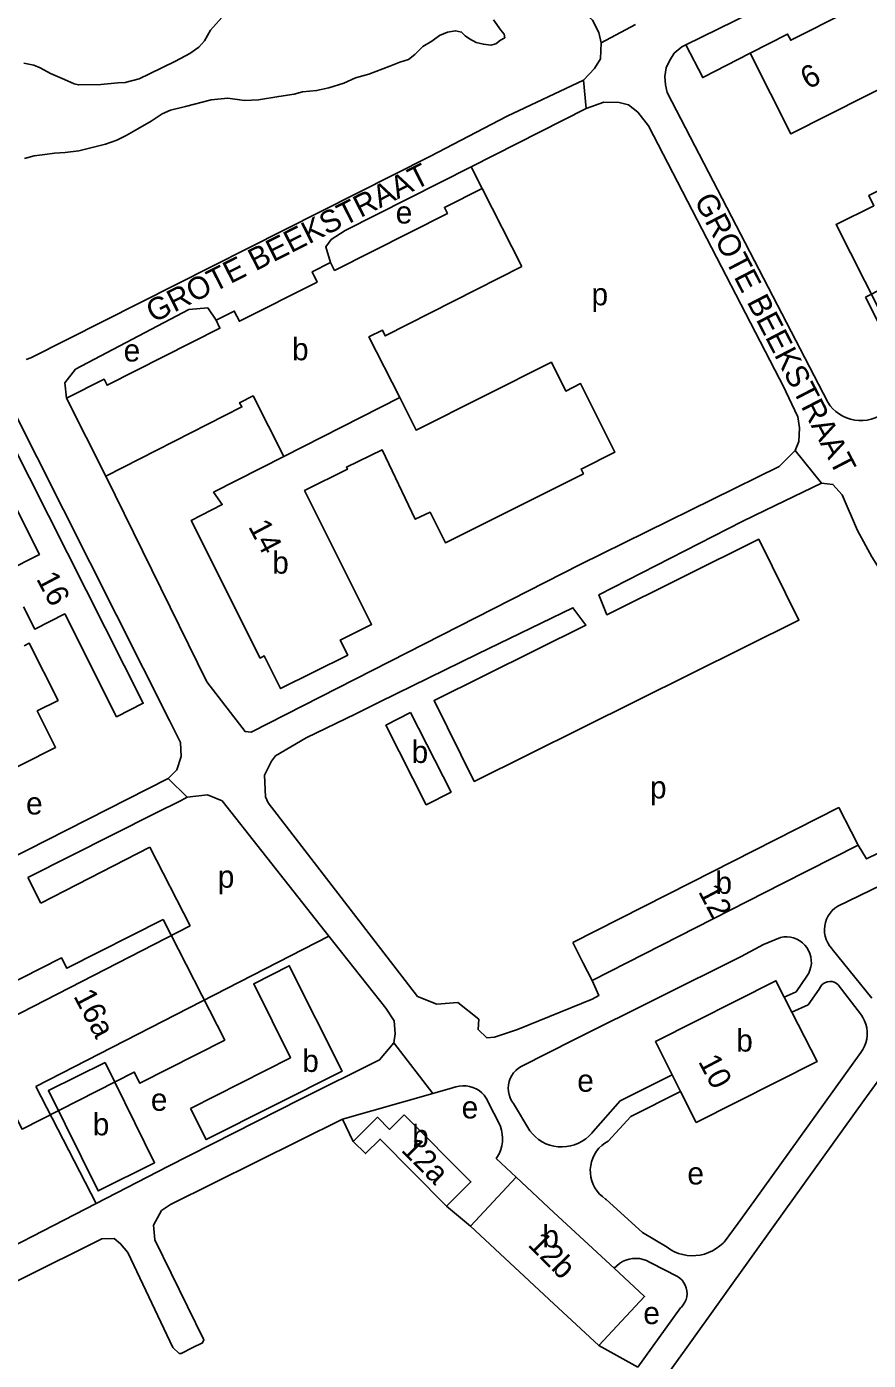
# Model space of a CAD drawing. Extents: x 158142 to 159655, y 385262 to 387204.
# Drawn here: x 158905.5 to 159056.3, y 386164.4 to 386403.5 of the extents above; entities that cross this region are included whole.
import ezdxf

# ---------------------------------------------------------------- set-up
doc = ezdxf.new("R2010")
doc.units = 0
for name, color, linetype in [('BLT_Basislijn', 7, 'Continuous'), ('BLT_Bebouwing', 7, 'Continuous'), ('BLT_Centroide', 7, 'Continuous'), ('BLT_Huisnummer', 7, 'Continuous'), ('BLT_Huisnummer_zonder_bebouwing', 7, 'Continuous'), ('BLT_Onderverdeling_panden', 7, 'Continuous'), ('BLT_Plantopo', 7, 'Continuous'), ('BLT_Straatnaam_verkleind', 7, 'Continuous'), ('BLT_Vlakafsluiter', 7, 'Continuous')]:
    doc.layers.add(name, color=color, linetype=linetype)

msp = doc.modelspace()

# ---------------------------------------------------------------- linework, layer by layer
at = {"layer": 'BLT_Basislijn'}
for p, q in [((159020.29, 386391.67), (159049.1, 386336.14)), ((158985.14, 386378.37), (159005.77, 386388.83)), ((158987.12, 386374.45), (158985.14, 386378.37)), ((158927.54, 386256.37), (158908.01, 386246.35)), ((158927.54, 386256.37), (158934.79, 386242.24)), ((158905.66, 386250.93), (158908.01, 386246.35)), ((158934.79, 386242.24), (158891.45, 386220.02)), ((158959.66, 386240.41), (158907.15, 386213.49)), ((159037.56, 386238.92), (159033.57, 386236.8)), ((159040.58, 386240.2), (159037.56, 386238.92)), ((159049.87, 386238.11), (159056.95, 386229.28)), ((159045.34, 386233.23), (159043.4, 386230.42)), ((159050.92, 386231.72), (159055.1, 386226.26)), ((159043.4, 386230.42), (159041.27, 386229.5)), ((159035.8, 386192.82), (159054.98, 386219.53)), ((158907.15, 386213.49), (158917.92, 386192.49)), ((158981.83, 386213.2), (158978.29, 386212.19)), ((158988.33, 386210.42), (158990.13, 386206.93)), ((158992.74, 386210.41), (158995.65, 386205.54)), ((159055.55, 386210.96), (159039.28, 386188.33)), ((158962.1, 386207.59), (158964.03, 386203.58)), ((158989.61, 386200.54), (158993.2, 386197.21)), ((158980.75, 386192.01), (158985.01, 386188.42)), ((159035.8, 386192.82), (159033.02, 386188.95)), ((159033.02, 386188.95), (159030.48, 386185.57)), ((159035.84, 386183.43), (159039.28, 386188.33)), ((159017.36, 386181.85), (159022.15, 386179.38)), ((159008.04, 386167), (159015.04, 386163.12))]:
    msp.add_line(p, q, dxfattribs=at)
for points in [[(159008.44, 386400.57), (159008.02, 386402.46), (159006.91, 386404.66), (158996.01, 386414.53), (158969.85, 386437.02)], [(159023.64, 386400.21), (159061.09, 386418.61), (159063, 386418.33), (159065.21, 386414.36)], [(158904.98, 386396.94), (158906.76, 386396.58), (158907.93, 386396.1), (158909.73, 386395.11), (158912.24, 386393.99), (158913.98, 386393.24), (158914.77, 386393.03), (158918.77, 386393.14), (158921.8, 386393.4), (158923.12, 386393.45), (158925.66, 386394.13), (158927.52, 386395.02), (158932.14, 386397.3), (158934.74, 386398.65), (158936.33, 386399.79), (158937.34, 386400.93), (158938.41, 386402.84), (158940.98, 386405.71)], [(158989.13, 386404.73), (158990.46, 386402.85), (158991.05, 386402.13), (158991.18, 386401.51), (158990.39, 386401.09), (158989.6, 386400.43), (158988.66, 386400.16), (158987.35, 386400.33), (158986.08, 386400.66), (158984.83, 386401.28), (158984.06, 386401.86), (158983.45, 386402.51), (158982.35, 386402.74), (158980.89, 386402.5), (158979.47, 386401.89), (158978.1, 386400.9), (158976.48, 386399.93), (158975.04, 386398.48), (158973.91, 386397.61), (158972.34, 386397.12), (158970.56, 386396.42), (158966.81, 386394.97), (158964.45, 386394.3), (158962.35, 386393.34), (158959.65, 386392.52), (158957.46, 386392.02), (158954.93, 386391.78), (158953.4, 386391.37), (158950.68, 386390.99), (158947.03, 386390.35), (158944.53, 386390.23), (158941.54, 386390.66), (158938.55, 386390.39), (158933.95, 386389.15), (158931.28, 386388.5), (158929.79, 386387.84), (158927.79, 386386.56), (158925.41, 386385.18), (158923.3, 386383.96), (158921.67, 386383.16), (158919.62, 386382.39), (158917.2, 386381.8), (158914.85, 386381.25), (158912.4, 386380.91), (158910.44, 386380.8), (158908.73, 386380.59), (158906.8, 386380.3), (158905.07, 386379.85)], [(159005.32, 386393.92), (159007.24, 386395.99), (159008.34, 386397.71), (159008.44, 386400.57)], [(159020.29, 386391.67), (159019.98, 386393.08), (159019.87, 386394.56), (159020.1, 386396.08), (159020.68, 386397.37), (159021.54, 386398.71), (159022.9, 386399.84), (159023.64, 386400.21)], [(159035.14, 386398.75), (159026.67, 386394.36), (159023.64, 386400.21)], [(158905.37, 386343.81), (158906.21, 386344.08), (158977.73, 386380.2), (158991.61, 386387.46), (159005.32, 386393.92)], [(159005.77, 386388.83), (159008.95, 386389.93), (159011.7, 386389.86), (159013.34, 386389.47), (159015.02, 386388.17), (159016.93, 386385.73), (159041.31, 386338.6)], [(158959.93, 386361.21), (158959.1, 386364.01), (158960.06, 386365.3), (158962.6, 386366.95), (158985.14, 386378.37)], [(158939.42, 386350.84), (158937.94, 386353.07), (158934.55, 386352.75), (158914.26, 386342.05), (158912.35, 386339.6), (158912.65, 386336.9)], [(159041.31, 386338.6), (159041.56, 386338.1), (159043.71, 386333.55), (159044, 386331.56), (159043.87, 386329.1), (159043.23, 386327.51)], [(158893.14, 386335.34), (158902.56, 386335.77), (158931.06, 386279.11), (158933.07, 386275.16), (158933.19, 386272.61), (158932.37, 386270.21), (158930.86, 386268.67)], [(159049.1, 386336.14), (159049.52, 386335.53), (159050.01, 386334.97), (159050.55, 386334.46), (159051.15, 386334.01), (159051.79, 386333.64), (159052.46, 386333.33), (159053.17, 386333.1), (159053.9, 386332.94), (159054.64, 386332.86), (159055.38, 386332.86), (159056.12, 386332.95), (159056.85, 386333.11), (159057.55, 386333.35), (159058, 386333.55)], [(159043.23, 386327.51), (159040.37, 386324.65), (159004.67, 386307.05), (158945.72, 386276.99)], [(158919.68, 386322.91), (158937.78, 386285.99), (158944.63, 386277.09), (158945.72, 386276.99)], [(159047.94, 386321.62), (159037.94, 386316.79), (159033.72, 386314.74), (159008.05, 386301.63), (159009.48, 386298.05), (159036.7, 386311.59), (159043.9, 386297.1), (158985.7, 386268.16), (158978.5, 386282.65), (159005.72, 386296.18), (159003.4, 386299.31), (158986.33, 386291.02), (158968.68, 386282.39), (158964.46, 386280.29), (158955.59, 386275.99), (158950.1, 386272.74), (158949.35, 386271.82), (158948.13, 386269.3), (158948.29, 386265.39), (158948.77, 386264.3), (158975.55, 386229.61), (158978.99, 386228.2), (158982.74, 386228.55)], [(159085.99, 386273.53), (159085.48, 386277.83), (159083.09, 386281.45), (159081.81, 386282.5), (159078.95, 386284.67), (159070.33, 386291.47), (159062.1, 386300.83), (159059.2, 386304.92), (159056.96, 386308.41), (159054.43, 386313.15), (159051.66, 386319.56), (159049.99, 386321.42), (159047.94, 386321.62)], [(159085.99, 386273.53), (159082.59, 386269.02), (159078.44, 386265.17), (159056.01, 386254.27), (159054.51, 386256.71)], [(158930.86, 386268.67), (158876.59, 386241.13)], [(159096.41, 386267.43), (159095.57, 386266.68), (159081.97, 386247.29), (159055.55, 386210.96)], [(158905.66, 386250.93), (158928.55, 386262.47), (158933.06, 386264.71), (158934.23, 386265.33)], [(158934.23, 386265.33), (158937.89, 386265.73), (158940.5, 386264.69), (158959.66, 386240.41)], [(159050.88, 386245.81), (159078.22, 386259.09), (159079.88, 386260.02), (159084, 386263.59), (159084.5, 386263.61), (159086.31, 386262.11)], [(158917.92, 386192.49), (158893.11, 386179.72), (158888.65, 386179.21), (158885.54, 386180.45), (158882.29, 386184.86), (158862.76, 386223.01), (158862.41, 386223.98), (158862.73, 386228.05), (158865.28, 386230.66), (158879.32, 386237.64), (158901.79, 386248.97)], [(159050.88, 386245.81), (159050.36, 386245.46), (159049.89, 386245.04), (159049.48, 386244.56), (159049.13, 386244.04), (159048.85, 386243.48), (159048.64, 386242.88), (159048.52, 386242.27), (159048.47, 386241.64), (159048.5, 386241.01), (159048.61, 386240.39), (159048.79, 386239.79), (159049.06, 386239.22), (159049.39, 386238.68), (159049.79, 386238.2), (159049.87, 386238.11)], [(158959.66, 386240.41), (158969.85, 386227.5), (158971.35, 386225.25), (158971.56, 386222.91), (158971.32, 386221.32)], [(159040.58, 386240.2), (159041.18, 386240.29), (159041.78, 386240.31), (159042.38, 386240.25), (159042.96, 386240.11), (159043.52, 386239.89), (159044.05, 386239.6), (159044.53, 386239.24), (159044.96, 386238.83), (159045.34, 386238.36), (159045.65, 386237.84), (159045.88, 386237.29), (159046.04, 386236.71), (159046.12, 386236.11), (159046.13, 386235.51), (159046.05, 386234.91), (159045.89, 386234.33), (159045.66, 386233.78), (159045.34, 386233.23)], [(158994.14, 386217.03), (159003.67, 386221.87), (159033.57, 386236.8)], [(159006.83, 386232.49), (159008.06, 386229.79), (159006.84, 386229.14), (158993.46, 386223.69), (158989.32, 386222.31), (158987.95, 386222.2), (158986.4, 386223.66), (158986.52, 386225.51), (158982.74, 386228.55)], [(159050.92, 386231.72), (159050.6, 386231.97), (159050.24, 386232.16), (159049.85, 386232.27), (159049.45, 386232.3), (159049.05, 386232.25), (159048.67, 386232.13), (159048.31, 386231.93), (159048.01, 386231.67), (159047.76, 386231.35), (159047.55, 386230.91)], [(159047.55, 386230.91), (159045.54, 386228.09), (159042.65, 386226.79)], [(159054.98, 386219.53), (159055.36, 386220.08), (159055.67, 386220.68), (159055.9, 386221.31), (159056.07, 386221.96), (159056.15, 386222.62), (159056.15, 386223.29), (159056.07, 386223.96), (159055.91, 386224.61), (159055.68, 386225.24), (159055.37, 386225.84), (159055.1, 386226.26)], [(158971.32, 386221.32), (158968.74, 386218.25), (158954.58, 386211.19), (158930.76, 386199.11)], [(158994.14, 386217.03), (158993.63, 386216.72), (158993.18, 386216.35), (158992.77, 386215.91), (158992.43, 386215.43), (158992.16, 386214.9), (158991.96, 386214.34), (158991.84, 386213.76), (158991.79, 386213.17), (158991.83, 386212.58), (158991.94, 386212), (158992.14, 386211.44), (158992.4, 386210.91), (158992.74, 386210.41)], [(159007.02, 386205.42), (159011.89, 386210.92), (159021.2, 386215.54)], [(158978.29, 386212.19), (158962.1, 386207.59)], [(158981.83, 386213.2), (158982.41, 386213.42), (158983.02, 386213.55), (158983.64, 386213.61), (158984.26, 386213.59), (158984.87, 386213.49), (158985.47, 386213.31), (158986.04, 386213.05), (158986.57, 386212.73), (158987.05, 386212.34), (158987.48, 386211.89), (158987.85, 386211.39), (158988.15, 386210.84), (158988.33, 386210.42)], [(159009.7, 386203.68), (159013.76, 386208.09), (159022.68, 386212.59)], [(158962.1, 386207.59), (158931.27, 386192.33), (158929.67, 386191.21), (158928.19, 386188.58), (158928.46, 386185.99), (158937.22, 386168.06), (158937, 386167.52), (158935.29, 386166.67), (158933.18, 386165.61), (158932.8, 386165.61), (158931.7, 386166.67), (158923.64, 386183.67), (158922.32, 386185.28), (158921.16, 386186.18), (158918.97, 386186.13), (158889.83, 386171.69)], [(158990.13, 386206.93), (158990.41, 386206.29), (158990.62, 386205.62), (158990.74, 386204.94), (158990.8, 386204.24), (158990.77, 386203.54), (158990.66, 386202.85), (158990.47, 386202.18), (158990.21, 386201.53), (158989.87, 386200.92), (158989.61, 386200.54)], [(158995.65, 386205.54), (158996.12, 386204.95), (158996.66, 386204.42), (158997.24, 386203.95), (158997.88, 386203.55), (158998.55, 386203.21), (158999.26, 386202.95), (158999.99, 386202.76), (159000.73, 386202.65), (159001.49, 386202.62), (159002.24, 386202.68), (159002.98, 386202.81), (159003.7, 386203.02), (159004.4, 386203.3), (159005.07, 386203.66), (159005.69, 386204.08), (159006.26, 386204.57), (159006.78, 386205.11), (159007.02, 386205.42)], [(159009.7, 386203.68), (159009.1, 386203.32), (159008.56, 386202.89), (159008.06, 386202.4), (159007.63, 386201.86), (159007.26, 386201.27), (159006.96, 386200.64), (159006.73, 386199.98), (159006.58, 386199.3), (159006.51, 386198.61), (159006.52, 386197.92), (159006.61, 386197.23), (159006.78, 386196.55), (159007.03, 386195.9), (159007.34, 386195.29), (159007.73, 386194.71), (159008.18, 386194.18), (159008.69, 386193.71), (159009.25, 386193.29), (159009.35, 386193.23)], [(158930.76, 386199.11), (158917.92, 386192.49)], [(159009.35, 386193.23), (159015.85, 386187.31), (159020.26, 386184.64)], [(159020.26, 386184.64), (159020.92, 386184.2), (159021.61, 386183.84), (159022.34, 386183.54), (159023.09, 386183.33), (159023.86, 386183.18), (159024.65, 386183.12), (159025.43, 386183.14), (159026.21, 386183.24), (159026.97, 386183.42), (159027.72, 386183.67), (159028.43, 386184), (159029.1, 386184.4), (159029.74, 386184.87), (159030.32, 386185.4), (159030.48, 386185.57)], [(159010.8, 386180.87), (159011.24, 386181.33), (159011.73, 386181.73), (159012.27, 386182.06), (159012.85, 386182.32), (159013.46, 386182.51), (159014.08, 386182.62), (159014.72, 386182.65), (159015.35, 386182.6), (159015.97, 386182.47), (159016.57, 386182.26), (159017.14, 386181.98), (159017.36, 386181.85)], [(159035.84, 386183.43), (159023.8, 386166.67), (159021.94, 386164.07), (159018.67, 386159.53)], [(159022.15, 386179.38), (159022.58, 386179.08), (159022.96, 386178.71), (159023.28, 386178.29), (159023.54, 386177.83), (159023.72, 386177.34), (159023.83, 386176.82), (159023.86, 386176.29), (159023.8, 386175.76), (159023.67, 386175.25), (159023.46, 386174.77), (159023.18, 386174.32), (159022.84, 386173.92), (159022.7, 386173.78), (159015.04, 386163.12)]]:
    msp.add_lwpolyline(points, dxfattribs=at)
msp.add_lwpolyline([(159055.82, 386354.97), (159081.32, 386367.94), (159088.64, 386353.63), (159062.98, 386340.74)], close=True, dxfattribs=at)
at = {"layer": 'BLT_Bebouwing'}
for p, q in [((158994.21, 386360.49), (158987.12, 386374.45)), ((158912.65, 386336.9), (158919.68, 386322.91)), ((159053.25, 386259.2), (159051.07, 386263.49)), ((159054.51, 386256.71), (159053.25, 386259.2)), ((159040.99, 386249.84), (159054.51, 386256.71)), ((159006.83, 386232.49), (159040.99, 386249.84)), ((159003.38, 386239.27), (159005.2, 386235.69)), ((159005.2, 386235.69), (159006.83, 386232.49)), ((159042.65, 386226.79), (159041.27, 386229.5)), ((159021.18, 386215.58), (159021.2, 386215.54)), ((159021.2, 386215.54), (159022.68, 386212.59)), ((159000, 386190.9), (158993.2, 386197.21)), ((159010.8, 386180.87), (159000, 386190.9))]:
    msp.add_line(p, q, dxfattribs=at)
for points in [[(159109.65, 386436.3), (159116.99, 386421.94), (159042.48, 386384.25), (159035.14, 386398.75)], [(159065.21, 386414.36), (159061.96, 386412.72), (159062.67, 386411.27), (159042.43, 386401.06), (159041.88, 386402.15), (159035.14, 386398.75)], [(158987.12, 386374.45), (158980.35, 386371.07), (158980.89, 386369.99), (158960.66, 386359.77), (158959.93, 386361.21)], [(158959.93, 386361.21), (158956.66, 386359.55), (158957.54, 386357.69), (158943.62, 386350.66), (158942.69, 386352.49), (158939.42, 386350.84)], [(158972.36, 386336.99), (158966.83, 386347.87), (158969.24, 386349.09), (158969.77, 386348.05), (158994.21, 386360.49)], [(158939.42, 386350.84), (158940.12, 386349.4), (158919.9, 386339.19), (158919.35, 386340.27), (158912.65, 386336.9)], [(158951.59, 386326.43), (158938.99, 386320.02), (158940.54, 386317.79), (158934.99, 386314.97), (158947.34, 386290.28), (158948.08, 386290.65), (158951, 386284.8), (158963.04, 386290.82), (158961.7, 386293.5), (158967.32, 386296.31), (158955.3, 386320.31), (158962.97, 386324.14), (158962.79, 386324.5), (158969.21, 386327.6), (158975.14, 386315.17), (158977.78, 386316.43), (158980.53, 386310.94), (159005.28, 386323.33), (159004.87, 386324.16), (159010.93, 386327.2), (159004.77, 386339.48), (159002.12, 386338.15), (158999.55, 386343.31), (158975.29, 386331.16), (158972.36, 386336.99)], [(158919.68, 386322.91), (158944.05, 386335.31), (158943.66, 386336.07), (158946.06, 386337.29), (158951.59, 386326.43)], [(158902.57, 386329.34), (158926.37, 386282.18), (158921.6, 386279.77), (158912.3, 386298.2), (158906.93, 386295.47), (158904.9, 386299.49)], [(158901.74, 386305.82), (158907.76, 386308.86), (158898.47, 386327.27)], [(158905.05, 386292.48), (158905.94, 386292.93), (158911.11, 386282.69), (158907.37, 386280.8), (158910.67, 386274.26), (158880.05, 386258.81)], [(159051.07, 386263.49), (159024.5, 386250), (159003.38, 386239.27)], [(159041.27, 386229.5), (159039.79, 386232.41), (159018.18, 386221.52), (159021.18, 386215.58)], [(159022.68, 386212.59), (159025.5, 386207.01), (159047.16, 386217.93), (159042.65, 386226.79)], [(158964.03, 386203.58), (158968.35, 386207.94), (158970.53, 386205.78), (158973.14, 386208.41)], [(158973.14, 386208.41), (158985.11, 386196.34), (158980.75, 386192.01)], [(158980.75, 386192.01), (158968.83, 386204.02), (158966.21, 386201.42), (158964.03, 386203.58)], [(158993.2, 386197.21), (158985.01, 386188.42)], [(158985.01, 386188.42), (159000, 386174.48), (159008.04, 386167)], [(159008.04, 386167), (159016.23, 386175.82), (159010.8, 386180.87)]]:
    msp.add_lwpolyline(points, dxfattribs=at)
for points in [[(158974.3, 386280.51), (158969.84, 386278.24), (158977.09, 386263.98), (158981.55, 386266.24)], [(158934.84, 386209.51), (158937.65, 386203.93), (158962.03, 386216.21), (158952.56, 386235.1), (158946.17, 386231.87), (158952.76, 386218.61)], [(158919.56, 386217.78), (158909.38, 386212.72), (158918.3, 386194.75), (158928.42, 386199.78)]]:
    msp.add_lwpolyline(points, close=True, dxfattribs=at)
at = {"layer": 'BLT_Onderverdeling_panden'}
msp.add_line((158972.36, 386336.99), (158951.59, 386326.43), dxfattribs=at)
at = {"layer": 'BLT_Plantopo'}
for points in [[(159116.59, 386409.22), (159085.8, 386393.7), (159088.1, 386389.15), (159056.43, 386373.19), (159057.32, 386371.38), (159050.57, 386368.04), (159060.77, 386347.79), (159074.31, 386354.62), (159075.09, 386353.07), (159081.2, 386355.82), (159079.32, 386359.4), (159091.59, 386365.71), (159085.18, 386378.43), (159092.11, 386381.91), (159089.73, 386386.63), (159098.15, 386390.88), (159110.74, 386365.89), (159130.93, 386376.07), (159124.61, 386388.59), (159128.07, 386390.33), (159125.08, 386396.27), (159123.52, 386395.49)], [(158929.96, 386243.43), (158912.69, 386234.65), (158911.72, 386236.55), (158893.69, 386227.38), (158904.65, 386205.84), (158924.75, 386216.06), (158925.78, 386214.04), (158940.98, 386221.77)]]:
    msp.add_lwpolyline(points, close=True, dxfattribs=at)
at = {"layer": 'BLT_Vlakafsluiter'}
for p, q in [((159014.61, 386403.9), (159008.44, 386400.57)), ((159005.77, 386388.83), (159005.32, 386393.92)), ((159047.94, 386321.62), (159043.23, 386327.51)), ((158930.86, 386268.67), (158934.23, 386265.33)), ((158978.29, 386212.19), (158971.32, 386221.32))]:
    msp.add_line(p, q, dxfattribs=at)

# ---------------------------------------------------------------- texts
at = {"layer": 'BLT_Centroide'}
for s, p in [('e', (158971.63, 386368.19)), ('p', (159006.73, 386353.52)), ('e', (158922.86, 386343.45)), ('b', (158953.05, 386343.67)), ('b', (158949.5, 386305.41)), ('b', (158974.48, 386271.47)), ('p', (159017.21, 386265.11)), ('e', (158905.37, 386262.24)), ('p', (158939.74, 386249.1)), ('b', (159028.95, 386248)), ('b', (159032.67, 386219.72)), ('b', (158954.88, 386216.07)), ('e', (159004.17, 386212.52)), ('e', (158927.74, 386209.11)), ('e', (158983.45, 386207.73)), ('b', (158917.32, 386204.7)), ('b', (158974.58, 386202.59)), ('e', (159023.91, 386195.9)), ('b', (158997.92, 386184.62)), ('e', (159016.01, 386170.86))]:
    msp.add_text(s, height=4, dxfattribs=at).set_placement(p)
at = {"layer": 'BLT_Huisnummer'}
for s, rotation, p in [('6', 27.8253, (159045.54, 386392.16)), ('14', 297.8252, (158945.13, 386313.85)), ('16', 297.8252, (158907.12, 386304.51)), ('12', 297.8252, (159025.78, 386248.42)), ('10', 297.8252, (159025.78, 386217.95)), ('12a', 314.7942, (158972.43, 386201.96)), ('12b', 314.7942, (158995.14, 386184.99))]:
    msp.add_text(s, height=4, rotation=rotation, dxfattribs=at).set_placement(p)
at = {"layer": 'BLT_Huisnummer_zonder_bebouwing'}
msp.add_text('16a', height=4, rotation=297.8252, dxfattribs=at).set_placement((158913.79, 386229.68))
at = {"layer": 'BLT_Straatnaam_verkleind'}
for rotation, p in [(26.907, (158928.21, 386350.32)), (297.407, (159025.05, 386372.37))]:
    msp.add_text('GROTE BEEKSTRAAT', height=4, rotation=rotation, dxfattribs=at).set_placement(p)

doc.saveas('drawing.dxf')
